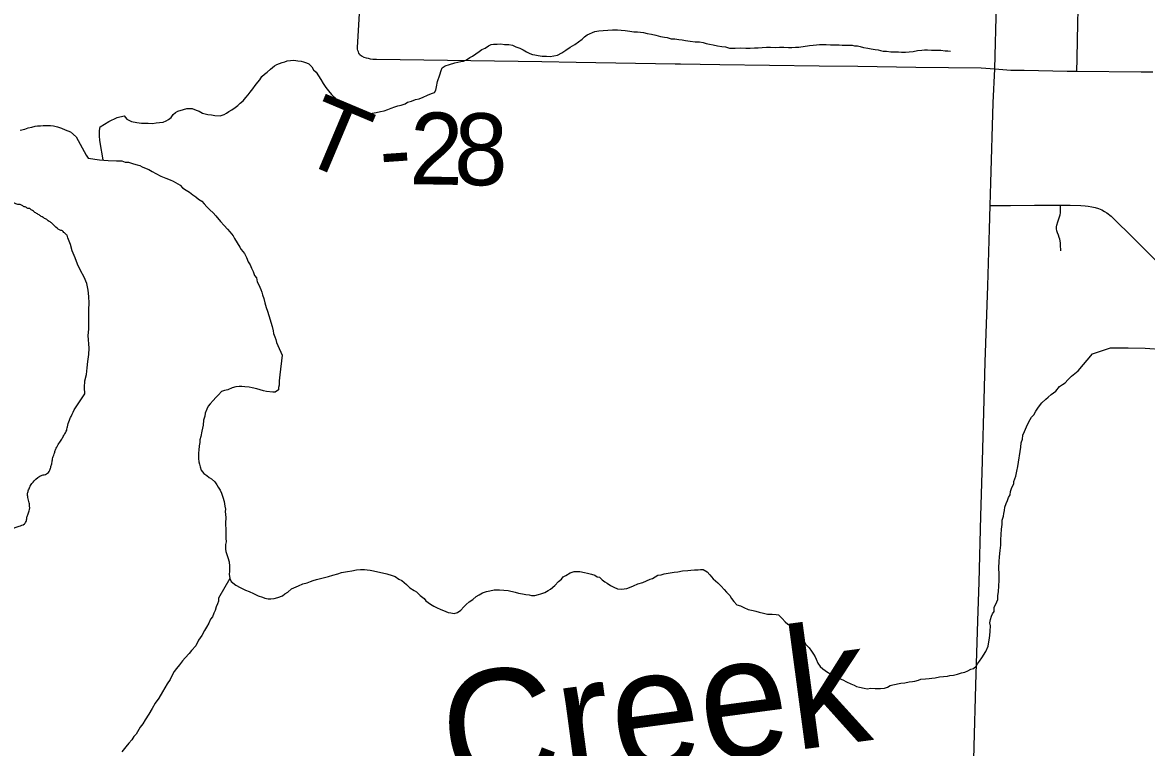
# Model space of a CAD drawing. Extents: x -483 to 680, y 0 to 440.
# Drawn here: x 289.15 to 333.54, y 248.81 to 277.45 of the extents above; entities that cross this region are included whole.
import ezdxf

# ---------------------------------------------------------------- set-up
doc = ezdxf.new("R2010")
doc.units = 0
for name, color, linetype in [('GM_X_City_Street', 7, 'Continuous'), ('GM_X_County_Road', 7, 'Continuous'), ('GM_X_Minor_Lake', 7, 'Continuous'), ('GM_X_Minor_River', 7, 'Continuous'), ('GM_X_Minor_River_Text', 7, 'Continuous'), ('GM_X_State_Route', 7, 'Continuous'), ('GM_X_Township_Road', 7, 'Continuous'), ('GM_X_Township_Road_Text', 7, 'Continuous')]:
    doc.layers.add(name, color=color, linetype=linetype)

msp = doc.modelspace()

# ---------------------------------------------------------------- linework, layer by layer
at = {"layer": 'GM_X_City_Street'}
for points in [[(330.796, 275.52), (330.806, 276.016), (330.82, 276.762), (330.858, 278.625), (330.866, 279.092), (330.88, 279.557), (330.893, 280.303), (330.913, 281.328), (330.946, 282.726), (330.972, 283.783), (330.986, 284.406), (331.031, 286.454), (331.045, 287.293), (331.074, 288.287), (331.102, 289.84), (331.156, 292.171), (331.166, 292.627)], [(327.363, 270.222), (327.903, 270.223), (328.173, 270.223), (329.119, 270.225), (330.149, 270.226), (330.53, 270.226), (330.948, 270.221), (331.116, 270.211), (331.241, 270.196), (331.383, 270.171), (331.519, 270.138), (331.639, 270.1), (331.773, 270.044), (331.881, 269.987), (331.969, 269.929), (332.144, 269.797), (332.334, 269.617), (332.914, 269.045), (333.406, 268.551), (333.827, 268.127), (334.309, 267.648), (334.625, 267.333)], [(330.162, 268.43), (330.15, 268.668), (330.146, 268.735), (330.133, 268.821), (330.12, 268.882), (330.097, 268.958), (330.06, 269.046), (330.02, 269.136), (329.998, 269.211), (329.985, 269.29), (329.987, 269.37), (330.002, 269.445), (330.037, 269.568), (330.106, 269.767), (330.132, 269.855), (330.142, 269.932), (330.149, 270.088), (330.149, 270.226)]]:
    msp.add_lwpolyline(points, dxfattribs=at)
at = {"layer": 'GM_X_County_Road'}
for points in [[(327.548, 275.621), (328.186, 275.564), (328.708, 275.559), (330.413, 275.523), (330.796, 275.52)], [(330.796, 275.52), (333.33, 275.5), (333.797, 275.499)]]:
    msp.add_lwpolyline(points, dxfattribs=at)
at = {"layer": 'GM_X_Minor_Lake'}
msp.add_lwpolyline([(291.454, 262.542), (291.617, 262.783), (291.6, 263.035), (291.617, 263.286), (291.684, 263.538), (291.7, 263.807), (291.734, 264.059), (291.767, 264.328), (291.783, 264.579), (291.749, 265.083), (291.766, 265.335), (291.765, 266.107), (291.782, 266.359), (291.765, 266.628), (291.748, 266.879), (291.697, 267.131), (291.58, 267.383), (291.445, 267.652), (291.327, 267.903), (291.227, 268.155), (291.109, 268.424), (291.041, 268.675), (290.94, 268.944), (290.913, 269.044)], dxfattribs=at)
for points in [[(290.913, 269.044), (290.892, 269.058), (290.836, 269.117), (290.78, 269.156), (290.725, 269.214), (290.668, 269.235), (290.296, 269.528), (290.24, 269.568), (290.165, 269.608), (290.11, 269.666), (290.053, 269.686), (289.997, 269.726), (289.922, 269.765), (289.81, 269.844), (289.736, 269.884), (289.679, 269.923), (289.605, 269.963), (289.549, 270.021), (289.493, 270.042), (289.437, 270.1), (289.361, 270.102), (289.305, 270.141), (289.249, 270.161), (289.193, 270.182), (289.137, 270.221), (289.024, 270.262), (288.967, 270.263), (288.892, 270.284), (288.835, 270.304), (288.76, 270.325), (288.703, 270.327), (288.646, 270.347), (288.59, 270.348), (288.477, 270.389), (288.42, 270.391), (288.363, 270.411), (288.306, 270.412), (288.25, 270.433), (288.193, 270.415), (288.079, 270.418), (288.002, 270.382), (287.887, 270.347), (287.714, 270.237), (287.636, 270.182), (287.5, 270.052), (287.442, 269.997), (287.384, 269.941), (287.325, 269.867), (287.285, 269.792), (287.246, 269.736), (287.205, 269.623), (287.166, 269.567), (287.084, 269.341), (287.083, 269.284), (287.062, 269.228), (287.023, 269.172), (286.962, 269.003), (286.923, 268.947), (286.864, 268.872), (286.843, 268.816), (286.804, 268.741), (286.783, 268.684), (286.762, 268.609), (286.742, 268.553), (286.739, 268.439), (286.718, 268.344), (286.716, 268.287), (286.677, 268.231), (286.656, 268.156), (286.577, 268.044), (286.5, 267.989), (286.424, 267.972), (286.367, 267.954), (286.31, 267.956), (286.197, 267.996), (286.085, 268.075), (286.03, 268.152), (285.974, 268.192), (285.918, 268.25), (285.862, 268.27), (285.806, 268.31), (285.75, 268.349)], [(287.462, 256.453), (287.562, 256.622), (287.622, 256.753), (287.664, 256.885), (287.649, 257.056), (287.768, 257.243), (287.903, 257.316), (288.056, 257.35), (288.19, 257.365), (288.399, 257.378), (288.532, 257.375), (288.705, 257.427), (289.012, 257.552), (289.224, 257.641), (289.304, 257.772), (289.326, 257.905), (289.368, 258.037), (289.429, 258.206), (289.433, 258.339), (289.417, 258.472), (289.366, 258.683), (289.351, 258.854), (289.393, 258.986), (289.454, 259.136), (289.611, 259.341), (289.921, 259.561), (290.094, 259.613), (290.231, 259.762), (290.273, 259.913), (290.314, 260.045), (290.338, 260.215), (290.4, 260.403), (290.442, 260.535), (290.502, 260.667), (290.622, 260.872), (290.721, 261.022), (290.801, 261.172), (290.88, 261.303), (290.923, 261.473), (291.006, 261.736), (291.067, 261.887), (291.454, 262.542)]]:
    msp.add_spline(points, degree=3, dxfattribs=at)
at = {"layer": 'GM_X_Minor_River'}
for points in [[(304.513, 274.346), (304.667, 274.399), (304.82, 274.432), (304.974, 274.504), (305.147, 274.575), (305.301, 274.647), (305.416, 274.681), (305.475, 274.775), (305.498, 274.907), (305.542, 275.115), (305.626, 275.379), (305.688, 275.548), (305.729, 275.661), (305.845, 275.734), (306.017, 275.786), (306.228, 275.856), (306.458, 275.906), (306.572, 275.922), (306.688, 275.976), (306.823, 276.067), (306.92, 276.121), (307.191, 276.303), (307.288, 276.377), (307.422, 276.43), (307.558, 276.521), (307.655, 276.575), (307.75, 276.592), (307.902, 276.587), (308.035, 276.602), (308.186, 276.579), (308.357, 276.574), (308.508, 276.551), (308.64, 276.49), (308.79, 276.429), (308.921, 276.368), (309.052, 276.288), (309.183, 276.227), (309.295, 276.186), (309.39, 276.164), (309.522, 276.141), (309.673, 276.118), (309.844, 276.113), (309.996, 276.109), (310.129, 276.124), (310.282, 276.158), (310.456, 276.248), (310.611, 276.357), (310.785, 276.466), (310.959, 276.575), (311.114, 276.685), (311.25, 276.795), (311.348, 276.887), (311.445, 276.961), (311.753, 277.085), (311.905, 277.118), (312.077, 277.133), (312.267, 277.146), (312.457, 277.16), (312.647, 277.154), (312.799, 277.15), (312.95, 277.126), (313.139, 277.102), (313.291, 277.079), (313.442, 277.074), (313.67, 277.049), (313.82, 277.006), (313.991, 276.982), (314.16, 276.94), (314.349, 276.896), (314.5, 276.873), (314.613, 276.851), (314.764, 276.808), (314.916, 276.804), (315.067, 276.78), (315.199, 276.758), (315.332, 276.735), (315.521, 276.71), (315.71, 276.686), (315.881, 276.681), (316.032, 276.658), (316.145, 276.616), (316.277, 276.593), (316.429, 276.57), (316.598, 276.527), (316.768, 276.503), (316.92, 276.48), (317.07, 276.438), (317.298, 276.431), (317.507, 276.444), (317.716, 276.438), (317.887, 276.433), (318.058, 276.447), (318.21, 276.443), (318.362, 276.458), (318.534, 276.472), (318.686, 276.467), (318.894, 276.461), (319.047, 276.476), (319.217, 276.471), (319.407, 276.465), (319.54, 276.462)], [(319.54, 276.462), (319.673, 276.477), (319.806, 276.473), (320.226, 276.537), (320.378, 276.552), (320.511, 276.567), (320.626, 276.583), (320.721, 276.58), (320.892, 276.575), (321.062, 276.57), (321.233, 276.565), (321.404, 276.56), (321.518, 276.557), (321.632, 276.554), (321.783, 276.549), (321.916, 276.545), (322.011, 276.524), (322.124, 276.52), (322.238, 276.498), (322.369, 276.456), (322.54, 276.432), (322.672, 276.41), (322.823, 276.386), (322.937, 276.364), (323.031, 276.342), (323.144, 276.32), (323.277, 276.316), (323.447, 276.292), (323.618, 276.287), (323.751, 276.283), (323.865, 276.28), (324.017, 276.276), (324.169, 276.29), (324.321, 276.305), (324.493, 276.338), (324.664, 276.352), (324.779, 276.368), (324.893, 276.365), (325.045, 276.36), (325.215, 276.355), (325.424, 276.349), (325.594, 276.326), (325.689, 276.323), (325.803, 276.32)], [(292.33, 272.016), (292.216, 272.704), (292.2, 272.799), (292.186, 272.952), (292.188, 273.047), (292.192, 273.18), (292.216, 273.331), (292.563, 273.53), (292.891, 273.692), (293.159, 273.76), (293.268, 273.624), (293.456, 273.542), (293.664, 273.498), (293.853, 273.474), (293.986, 273.47), (294.119, 273.466), (294.289, 273.461), (294.423, 273.477), (294.556, 273.492), (294.708, 273.506), (294.824, 273.56), (294.92, 273.614), (295.018, 273.688), (295.097, 273.819), (295.194, 273.892), (295.291, 273.946), (295.502, 274.016), (295.636, 274.05), (295.75, 274.047), (295.845, 274.044), (296.014, 273.982), (296.126, 273.941), (296.257, 273.861), (296.465, 273.817), (296.616, 273.794), (296.748, 273.771), (296.957, 273.765), (297.11, 273.818), (297.207, 273.872), (297.304, 273.926), (297.42, 273.999), (297.555, 274.09), (297.652, 274.163), (297.75, 274.256), (297.866, 274.347), (297.965, 274.478), (298.063, 274.589), (298.143, 274.701), (298.241, 274.831), (298.34, 274.961), (298.439, 275.091), (298.517, 275.184), (298.597, 275.315), (298.714, 275.406), (298.811, 275.48), (298.948, 275.609), (299.103, 275.738), (299.2, 275.792), (299.296, 275.827), (299.411, 275.862), (299.507, 275.897), (299.603, 275.932), (299.736, 275.947), (299.869, 275.963), (300.021, 275.939), (300.153, 275.916), (300.247, 275.895), (300.36, 275.854), (300.454, 275.813), (300.583, 275.695), (300.637, 275.579), (300.748, 275.481), (300.839, 275.345), (300.929, 275.191), (301.02, 275.036), (301.129, 274.881), (301.239, 274.745), (301.349, 274.608), (301.46, 274.491), (301.552, 274.393), (301.698, 274.18), (301.808, 274.063), (301.902, 274.003), (302.013, 273.924), (302.164, 273.881), (302.334, 273.838), (302.428, 273.817), (302.618, 273.83), (302.79, 273.844), (302.961, 273.859), (303.114, 273.892), (303.286, 273.925), (303.439, 273.959), (303.573, 274.012), (303.708, 274.065), (303.861, 274.118), (303.976, 274.153), (304.11, 274.187), (304.263, 274.239), (304.36, 274.294), (304.513, 274.346)], [(289.053, 273.195), (289.244, 273.228), (289.378, 273.282), (289.512, 273.316), (289.646, 273.351), (289.741, 273.368), (289.855, 273.365), (289.97, 273.381), (290.083, 273.378), (290.254, 273.374), (290.368, 273.371), (290.538, 273.328), (290.688, 273.268), (290.839, 273.207), (291.046, 273.126)], [(291.268, 272.928), (291.046, 273.126)], [(291.268, 272.928), (291.67, 272.206), (291.743, 272.09), (292.197, 272.02), (292.538, 271.991), (292.86, 271.982), (293.069, 271.976), (293.201, 271.934), (293.333, 271.93), (293.54, 271.867), (293.672, 271.825), (293.785, 271.803), (293.879, 271.743), (294.029, 271.682), (294.142, 271.641), (294.272, 271.561), (294.422, 271.48), (294.609, 271.38), (294.815, 271.298), (294.984, 271.236), (295.097, 271.176), (295.377, 271.016), (295.469, 270.918), (295.618, 270.819), (295.749, 270.739), (295.879, 270.64), (295.99, 270.561), (296.102, 270.463), (296.232, 270.383), (296.324, 270.285), (296.435, 270.168), (296.545, 270.051), (296.675, 269.933), (296.786, 269.816), (296.969, 269.582), (297.116, 269.426), (297.245, 269.289), (297.337, 269.172), (297.465, 269.017), (297.519, 268.92), (297.628, 268.746), (297.737, 268.572), (297.791, 268.475), (297.92, 268.319), (297.991, 268.165), (298.062, 267.992), (298.135, 267.876), (298.188, 267.741), (298.26, 267.606), (298.312, 267.452), (298.385, 267.355), (298.419, 267.202), (298.473, 267.105), (298.527, 266.99), (298.562, 266.894), (298.597, 266.798), (298.632, 266.683), (298.685, 266.548), (298.718, 266.376), (298.769, 266.184), (298.822, 266.05), (298.874, 265.877), (299.013, 265.436), (299.047, 265.264), (299.063, 265.168), (299.116, 265.034), (299.151, 264.919), (299.185, 264.804), (299.239, 264.688), (299.407, 264.308)], [(330.844, 263.692), (331.407, 264.365), (332.117, 264.595), (332.82, 264.597), (333.485, 264.581), (334.245, 264.524), (334.949, 264.526), (335.614, 264.528), (336.356, 264.548), (337.137, 264.567), (338.638, 264.53), (339.304, 264.533), (340.083, 264.513), (340.823, 264.457), (341.564, 264.401), (343.082, 264.287), (343.747, 264.252), (344.431, 264.216), (345.173, 264.217), (345.857, 264.219), (346.58, 264.239), (347.285, 264.279)], [(299.407, 264.308), (299.313, 263.524), (299.289, 263.296), (299.285, 263.125), (299.264, 263.03), (299.262, 262.935), (299.127, 262.843), (299.032, 262.845), (298.785, 262.869), (298.671, 262.891), (298.538, 262.932), (298.406, 262.973), (298.217, 263.015), (298.103, 263.037), (297.932, 263.06), (297.818, 263.062), (297.704, 263.065), (297.57, 263.049), (297.436, 263.013), (297.263, 262.941), (297.129, 262.906), (297.014, 262.871), (296.897, 262.74), (296.78, 262.628), (296.683, 262.516), (296.566, 262.386), (296.487, 262.292), (296.428, 262.179), (296.367, 262.009), (296.346, 261.895), (296.304, 261.744), (296.281, 261.535), (296.238, 261.308), (296.195, 261.099), (296.155, 260.967), (296.152, 260.853), (296.13, 260.72), (296.108, 260.549), (296.106, 260.454), (296.101, 260.226), (296.117, 260.092), (296.134, 259.997), (296.17, 259.901), (296.205, 259.767), (296.317, 259.631), (296.429, 259.552), (296.523, 259.474), (296.617, 259.415), (296.747, 259.298), (296.821, 259.182), (296.876, 259.086), (296.95, 258.97), (297.004, 258.854), (297.058, 258.701), (297.112, 258.528), (297.129, 258.433), (297.146, 258.337), (297.162, 258.223), (297.16, 258.128), (297.174, 257.899), (297.17, 257.67), (297.183, 257.385), (297.179, 257.213), (297.176, 257.08), (297.192, 256.928), (297.171, 256.833), (297.169, 256.738), (297.167, 256.643), (297.184, 256.547), (297.219, 256.432), (297.255, 256.317), (297.308, 256.144), (297.324, 255.973), (297.322, 255.878), (297.319, 255.764), (297.317, 255.649), (297.332, 255.478), (297.387, 255.362), (297.574, 255.225), (297.743, 255.126), (297.951, 255.026), (298.102, 254.966), (298.272, 254.886), (298.46, 254.806), (298.63, 254.745), (298.725, 254.704), (298.857, 254.683), (298.953, 254.68), (299.086, 254.697), (299.239, 254.731), (299.412, 254.804), (299.509, 254.878), (299.625, 254.951), (299.78, 255.081), (300.049, 255.189), (300.222, 255.28), (300.394, 255.315), (300.529, 255.369)], [(327.381, 253.86), (327.422, 253.992), (327.462, 254.086), (327.521, 254.18), (327.525, 254.352), (327.584, 254.464), (327.665, 254.653), (327.668, 254.805), (327.691, 254.976), (327.714, 255.185), (327.719, 255.413), (327.724, 255.66), (327.711, 255.908), (327.716, 256.156), (327.739, 256.345), (327.763, 256.592), (327.787, 256.801), (327.791, 257.011), (327.796, 257.22), (327.819, 257.429), (327.842, 257.619), (327.846, 257.79), (327.887, 257.941), (327.909, 258.055), (327.93, 258.169), (327.952, 258.301), (327.993, 258.453), (328.053, 258.566), (328.093, 258.679), (328.153, 258.792), (328.175, 258.925), (328.215, 259.038), (328.255, 259.132), (328.295, 259.226), (328.298, 259.322), (328.338, 259.416), (328.378, 259.529), (328.42, 259.719), (328.462, 259.908), (328.574, 260.667), (328.596, 260.838), (328.638, 260.989), (328.66, 261.141), (328.72, 261.292), (328.801, 261.48), (328.9, 261.669), (328.999, 261.857), (329.096, 261.95), (329.176, 262.1), (329.274, 262.25), (329.411, 262.419), (329.566, 262.568), (329.663, 262.642), (329.78, 262.753), (329.954, 262.883), (330.11, 263.069), (330.226, 263.143), (330.323, 263.217), (330.439, 263.329), (330.576, 263.478), (330.844, 263.692)], [(300.529, 255.369), (300.625, 255.405), (300.759, 255.44), (301.237, 255.563), (301.41, 255.616), (301.601, 255.669), (301.755, 255.722), (301.984, 255.755), (302.156, 255.79), (302.347, 255.823), (302.5, 255.839), (302.652, 255.836), (302.766, 255.833), (302.88, 255.812), (303.013, 255.79), (303.183, 255.748), (303.373, 255.706), (303.543, 255.664), (303.751, 255.602), (303.865, 255.561), (304.015, 255.463), (304.128, 255.403), (304.315, 255.247), (304.445, 255.111), (304.615, 255.012), (304.709, 254.953), (304.858, 254.816), (305.008, 254.699), (305.082, 254.602), (305.269, 254.464), (305.401, 254.385), (305.495, 254.345), (305.665, 254.265), (305.778, 254.225), (305.967, 254.144), (306.062, 254.123), (306.195, 254.101), (306.329, 254.136), (306.464, 254.228), (306.581, 254.359), (306.678, 254.452), (306.795, 254.564), (306.93, 254.656), (307.066, 254.767), (307.181, 254.841), (307.316, 254.914), (307.47, 254.967), (307.604, 255.003), (307.776, 255.037), (307.871, 255.035), (307.985, 255.032), (308.156, 255.028), (308.327, 255.006), (308.612, 254.942), (308.744, 254.901), (308.896, 254.879), (309.029, 254.857), (309.161, 254.835), (309.256, 254.814), (309.389, 254.811), (309.524, 254.846), (309.619, 254.882), (309.773, 254.935), (309.908, 255.009), (310.004, 255.064), (310.179, 255.212), (310.315, 255.361), (310.431, 255.454), (310.509, 255.547), (310.606, 255.602), (310.78, 255.713), (310.933, 255.766), (311.161, 255.761), (311.351, 255.719), (311.465, 255.697), (311.616, 255.656), (311.749, 255.615), (311.843, 255.556), (311.937, 255.535), (312.049, 255.437), (312.143, 255.359), (312.237, 255.3), (312.368, 255.202), (312.5, 255.142), (312.651, 255.081), (312.822, 255.058), (312.917, 255.075), (313.013, 255.092), (313.128, 255.128), (313.282, 255.2), (313.455, 255.273), (313.646, 255.326), (313.8, 255.398), (313.935, 255.452), (314.031, 255.488), (314.243, 255.617), (314.376, 255.633), (314.492, 255.668), (314.893, 255.736), (315.026, 255.752), (315.217, 255.786)], [(315.217, 255.786), (315.427, 255.8), (315.542, 255.816), (315.695, 255.832), (315.828, 255.829), (315.923, 255.846), (316.037, 255.844), (316.188, 255.745), (316.299, 255.628), (316.429, 255.473), (316.617, 255.317), (316.747, 255.181), (316.858, 255.045), (316.951, 254.948), (317.082, 254.811), (317.155, 254.696), (317.248, 254.579), (317.359, 254.444), (317.511, 254.402), (317.643, 254.342), (317.813, 254.262), (318.002, 254.22), (318.116, 254.198), (318.248, 254.157), (318.419, 254.116), (318.57, 254.074), (318.76, 254.07), (318.913, 254.067), (319.007, 254.045), (319.157, 253.909), (319.268, 253.773), (319.38, 253.676), (319.512, 253.615), (319.586, 253.519), (319.717, 253.383), (319.866, 253.227), (319.977, 253.072), (320.087, 252.879), (320.217, 252.743), (320.31, 252.608), (320.383, 252.492), (320.457, 252.395), (320.493, 252.299), (320.566, 252.145), (320.659, 252.01), (320.752, 251.913), (320.846, 251.854), (320.977, 251.756), (321.071, 251.715), (321.334, 251.557), (321.542, 251.477), (321.693, 251.397), (321.862, 251.317), (321.995, 251.276), (322.089, 251.217), (322.202, 251.195), (322.392, 251.153), (322.506, 251.132), (322.658, 251.147), (322.83, 251.143), (322.925, 251.141), (323.039, 251.139), (323.192, 251.154), (323.307, 251.19), (323.423, 251.264), (323.518, 251.28), (323.843, 251.349), (323.996, 251.365), (324.168, 251.399), (324.302, 251.415), (324.397, 251.432), (324.531, 251.467), (324.627, 251.503), (324.818, 251.518), (324.952, 251.534), (325.066, 251.551), (325.2, 251.567), (325.372, 251.601), (325.525, 251.617), (325.677, 251.632), (325.773, 251.649), (325.925, 251.665), (326.078, 251.7), (326.232, 251.753), (326.366, 251.788), (326.481, 251.843), (326.597, 251.897), (326.712, 251.933), (326.809, 252.026), (326.868, 252.12), (326.946, 252.213), (327.044, 252.344), (327.202, 252.607), (327.283, 252.815), (327.304, 252.91), (327.326, 253.042), (327.349, 253.232), (327.371, 253.403), (327.376, 253.612), (327.359, 253.727), (327.381, 253.86)], [(297.332, 255.478), (296.897, 254.707), (296.894, 254.593), (296.854, 254.479), (296.794, 254.367), (296.753, 254.215), (296.713, 254.121), (296.653, 253.97), (296.574, 253.877), (296.514, 253.726), (296.415, 253.556), (296.336, 253.425), (296.237, 253.237), (296.1, 253.05), (296, 252.823), (295.824, 252.637), (295.727, 252.525), (295.571, 252.357), (295.473, 252.226), (295.356, 252.076), (295.238, 251.926), (295.14, 251.814), (295.061, 251.664), (294.981, 251.494), (294.863, 251.326), (294.685, 251.006), (294.528, 250.762), (294.39, 250.556), (294.272, 250.349), (294.133, 250.124), (293.995, 249.898), (293.897, 249.748), (293.799, 249.617), (293.641, 249.335), (293.543, 249.242), (293.464, 249.111), (293.347, 248.98), (293.23, 248.83), (293.074, 248.643)]]:
    msp.add_lwpolyline(points, dxfattribs=at)
at = {"layer": 'GM_X_State_Route'}
for points in [[(327.548, 275.621), (327.616, 278.175), (327.644, 279.815), (327.728, 283.645), (327.748, 284.539), (327.784, 286.125), (327.852, 289.3), (327.874, 290.505), (327.896, 291.415), (327.919, 292.551), (327.923, 292.704), (327.924, 292.754)], [(326.625, 242.754), (326.652, 245.336), (326.678, 246.827), (326.733, 248.845), (326.804, 251.267), (326.885, 253.814), (326.929, 255.336), (327.002, 257.944), (327.064, 260.118), (327.129, 262.541), (327.167, 264.031), (327.268, 267.043), (327.334, 269.279), (327.363, 270.222), (327.39, 271.112), (327.485, 274.279), (327.548, 275.621)]]:
    msp.add_lwpolyline(points, dxfattribs=at)
at = {"layer": 'GM_X_Township_Road'}
for points in [[(302.471, 276.182), (302.432, 276.242), (302.414, 276.293), (302.396, 276.337), (302.384, 276.394), (302.378, 276.462), (302.582, 279.828), (302.659, 281.713), (302.713, 283.389), (302.776, 285.312), (302.888, 288.584)], [(302.471, 276.182), (302.541, 276.125), (302.628, 276.082), (302.719, 276.052), (302.799, 276.032), (302.883, 276.015), (302.99, 276.005), (303.128, 276.005), (309.664, 275.909), (311.012, 275.886), (314.928, 275.819), (314.986, 275.819)], [(314.986, 275.819), (315.139, 275.816), (316.691, 275.793), (320.61, 275.74), (322.134, 275.717), (324.436, 275.682), (327.015, 275.657), (327.548, 275.621)]]:
    msp.add_lwpolyline(points, dxfattribs=at)

# ---------------------------------------------------------------- texts
at = {"layer": 'GM_X_Minor_River_Text'}
msp.add_text('Creek', height=4.7372, rotation=7.6238, dxfattribs=at).set_placement((306.034, 246.873))
at = {"layer": 'GM_X_Township_Road_Text'}
for s, rotation, p in [('T', 337.1711, (299.946, 272.044)), ('2', 359.0164, (304.42, 271.064)), ('8', 359.1946, (306.18, 271.034)), ('-', 3.984, (303.321, 270.984))]:
    msp.add_text(s, height=2.841, rotation=rotation, dxfattribs=at).set_placement(p)

doc.saveas('drawing.dxf')
